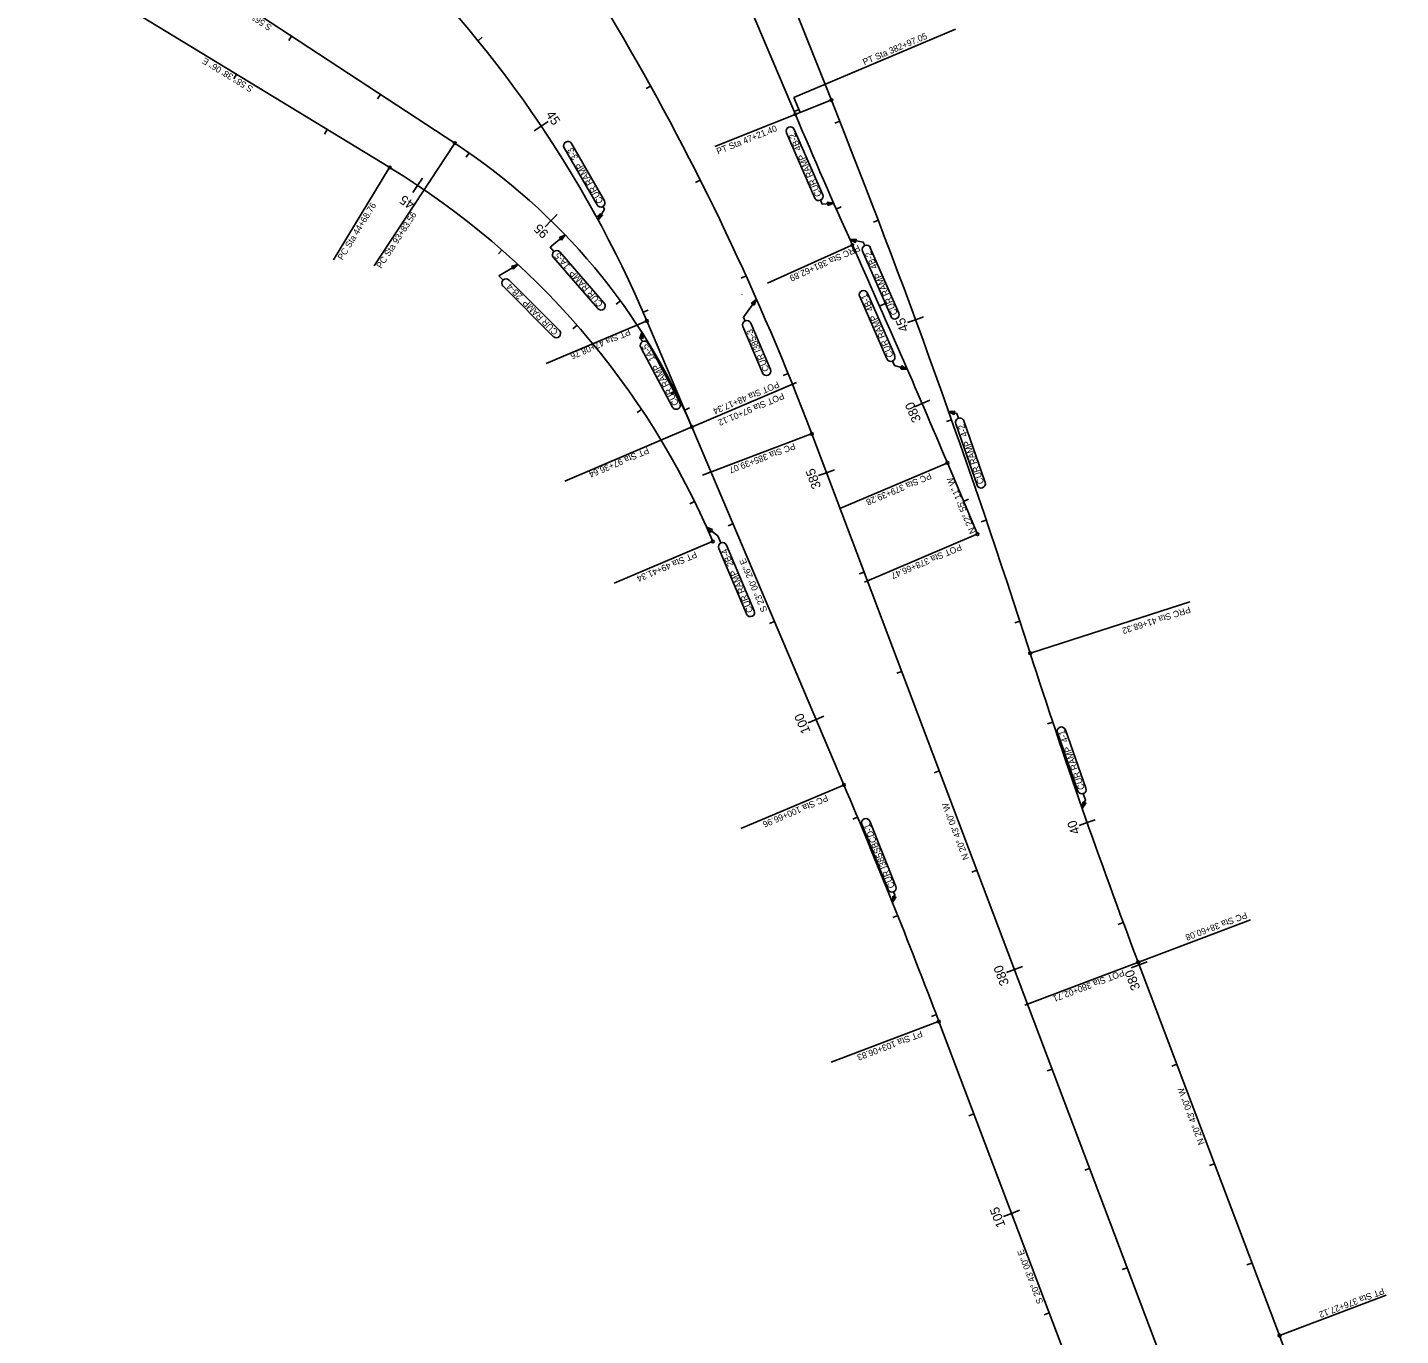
# Model space of a CAD drawing. Extents: x 1603540 to 1622629, y 1083934 to 1103503.
# Drawn here: x 1610826 to 1612118, y 1091966 to 1093197 of the extents above; entities that cross this region are included whole.
import ezdxf

# ---------------------------------------------------------------- set-up
doc = ezdxf.new("R2010")
doc.units = 0
for name, color, linetype in [('RD_EX_BldgChurch', 7, 'Continuous'), ('RD_EX_Fence_ChLk', 7, 'Continuous'), ('RD_EX_H2O', 7, 'Continuous'), ('RD_EX_Misc', 7, 'Continuous'), ('RD_HC_CL', 7, 'Continuous'), ('RD_PG_GR', 7, 'Continuous')]:
    doc.layers.add(name, color=color, linetype=linetype)

msp = doc.modelspace()

# ---------------------------------------------------------------- linework, layer by layer
at = {"layer": 'RD_EX_BldgChurch'}
for p, q in [((1611547.2, 1093131.3), (1611699.4, 1093195.7)), ((1611581.5, 1093128.4), (1611473, 1093085.2)), ((1611547.2, 1093131.3), (1611553.2, 1093117.1)), ((1611227.6, 1093087.2), (1611152.6, 1092972.9)), ((1611166.4, 1093064.3), (1611114.1, 1092978.5)), ((1611601.2, 1092991.9), (1611522.6, 1092956.5)), ((1611498.8, 1092945.8), (1611498.4, 1092945.7)), ((1611407.8, 1092920.6), (1611314.4, 1092880.9)), ((1611452.5, 1092821.6), (1611549.7, 1092862.9)), ((1611452.5, 1092821.6), (1611546.8, 1092861.7)), ((1611450.2, 1092820.7), (1611331.7, 1092770.3)), ((1611562.9, 1092814.3), (1611461.2, 1092775.8)), ((1611690.6, 1092786.9), (1611590.4, 1092744.6)), ((1611718.9, 1092719.9), (1611613.6, 1092675.3)), ((1611469.9, 1092713), (1611378.3, 1092674.1)), ((1611770.7, 1092608.8), (1611919.8, 1092656.6)), ((1611593.2, 1092483.9), (1611497.5, 1092443.3)), ((1611872.3, 1092317.9), (1611976.9, 1092357.5)), ((1611869.9, 1092317), (1611764.4, 1092277.1)), ((1611682.5, 1092261.4), (1611582.4, 1092223.5)), ((1612005.1, 1091966.6), (1612104.5, 1092004.2))]:
    msp.add_line(p, q, dxfattribs=at)
for centre in [(1611582.6, 1093128.9), (1611548.7, 1093115.4), (1611228.3, 1093088.3), (1611167.1, 1093065.3), (1611602.3, 1092992.4), (1611408.9, 1092921.1), (1611451.4, 1092821.2), (1611451.4, 1092821.2), (1611564.1, 1092814.8), (1611691.7, 1092787.4), (1611720.1, 1092720.3), (1611471, 1092713.5), (1611769.5, 1092608.4), (1611594.4, 1092484.4), (1611871.1, 1092317.5), (1611683.7, 1092261.8), (1612004, 1091966.2)]:
    msp.add_circle(centre, 1.25, dxfattribs=at)
at = {"layer": 'RD_EX_H2O'}
for p, q in [((1611074.8, 1093189), (1611072.1, 1093184.8)), ((1611250.2, 1093184.7), (1611254.1, 1093187.9)), ((1611023, 1093153.2), (1611020.4, 1093148.9)), ((1611158.5, 1093134.1), (1611155.7, 1093129.9)), ((1611412.5, 1093142), (1611408.2, 1093139.6)), ((1611547.6, 1093118.1), (1611552.2, 1093120)), ((1611309.7, 1093104.4), (1611316.3, 1093108.8)), ((1611590.5, 1093109), (1611585.9, 1093107.1)), ((1611108.4, 1093101.1), (1611105.7, 1093096.9)), ((1611309.7, 1093104.4), (1611303, 1093099.9)), ((1611241.9, 1093079.1), (1611239.1, 1093075)), ((1611193.4, 1093048.5), (1611197.8, 1093055.2)), ((1611193.4, 1093048.5), (1611189, 1093041.9)), ((1611459.2, 1093053.6), (1611454.8, 1093051.3)), ((1611318.9, 1093015.4), (1611324.5, 1093021.1)), ((1611361.6, 1093018.9), (1611365.9, 1093021.3)), ((1611587.2, 1093026.3), (1611591.8, 1093028.3)), ((1611318.9, 1093015.4), (1611313.3, 1093009.6)), ((1611626.7, 1093015.8), (1611622.1, 1093014)), ((1611272.7, 1092987.7), (1611269.4, 1092984)), ((1611502.4, 1092963.4), (1611497.8, 1092961.3)), ((1611384.2, 1092939.8), (1611380.1, 1092936.8)), ((1611405.5, 1092929.1), (1611410.1, 1092931.1)), ((1611627.9, 1092934.9), (1611632.5, 1092937)), ((1611343.3, 1092917), (1611339.5, 1092913.7)), ((1611661.8, 1092922.1), (1611654.3, 1092919.4)), ((1611661.8, 1092922.1), (1611669.3, 1092924.9)), ((1611541.8, 1092871.5), (1611537.2, 1092869.6)), ((1611436, 1092854.4), (1611431.6, 1092852.2)), ((1611404, 1092837.7), (1611399.9, 1092834.9)), ((1611444.6, 1092837.1), (1611449.2, 1092839.1)), ((1611667.9, 1092843.3), (1611660.6, 1092840.1)), ((1611667.9, 1092843.3), (1611675.3, 1092846.4)), ((1611695.6, 1092828), (1611690.9, 1092826.3)), ((1611577.9, 1092778.2), (1611570.4, 1092775.4)), ((1611577.9, 1092778.2), (1611585.4, 1092781)), ((1611453.9, 1092751), (1611449.4, 1092748.8)), ((1611707, 1092751.2), (1611711.6, 1092753.2)), ((1611728.3, 1092733.5), (1611723.6, 1092731.9)), ((1611490, 1092730.1), (1611485.4, 1092728.2)), ((1611613.3, 1092684.7), (1611608.6, 1092682.9)), ((1611529.1, 1092638.1), (1611524.5, 1092636.1)), ((1611759.8, 1092638.6), (1611755, 1092637)), ((1611648.7, 1092591.1), (1611644, 1092589.4)), ((1611568.2, 1092546), (1611560.8, 1092542.9)), ((1611568.2, 1092546), (1611575.6, 1092549.2)), ((1611790.8, 1092543.5), (1611786, 1092541.9)), ((1611684, 1092497.6), (1611679.4, 1092495.8)), ((1611607.2, 1092454), (1611602.6, 1092452)), ((1611823.1, 1092448.9), (1611815.6, 1092446.2)), ((1611823.1, 1092448.9), (1611830.7, 1092451.6)), ((1611719.4, 1092404.1), (1611714.7, 1092402.3)), ((1611645, 1092361.4), (1611640.4, 1092359.5)), ((1611857.1, 1092354.8), (1611852.4, 1092353.1)), ((1611754.8, 1092310.5), (1611747.3, 1092307.7)), ((1611754.8, 1092310.5), (1611762.3, 1092313.4)), ((1611872.1, 1092314.9), (1611864.6, 1092312.1)), ((1611872.1, 1092314.9), (1611879.6, 1092317.8)), ((1611681.3, 1092268.2), (1611676.6, 1092266.4)), ((1611790.2, 1092217), (1611785.5, 1092215.2)), ((1611907.4, 1092221.4), (1611902.8, 1092219.6)), ((1611716.6, 1092174.7), (1611712, 1092172.9)), ((1611942.8, 1092127.9), (1611938.1, 1092126.1)), ((1611825.5, 1092123.5), (1611820.9, 1092121.7)), ((1611752, 1092081.1), (1611744.5, 1092078.3)), ((1611752, 1092081.1), (1611759.5, 1092084)), ((1611860.9, 1092029.9), (1611856.2, 1092028.2)), ((1611978.2, 1092034.3), (1611973.5, 1092032.6)), ((1611787.4, 1091987.6), (1611782.7, 1091985.8))]:
    msp.add_line(p, q, dxfattribs=at)
at = {"layer": 'RD_HC_CL'}
for p, q in [((1611582.6, 1093128.9), (1611474, 1093401.3)), ((1610826.4, 1093352.1), (1611228.3, 1093088.3)), ((1611548.7, 1093115.4), (1611482.5, 1093272)), ((1610851.4, 1093257.7), (1611167.1, 1093065.3)), ((1611408.9, 1092921.1), (1611451.4, 1092821.2)), ((1611451.4, 1092821.2), (1611594.4, 1092484.4)), ((1612051.1, 1091527.2), (1611564.1, 1092814.8)), ((1611720.1, 1092720.3), (1611691.7, 1092787.4)), ((1612004, 1091966.2), (1611871.1, 1092317.5)), ((1611683.7, 1092261.8), (1611849.6, 1091823.2))]:
    msp.add_line(p, q, dxfattribs=at)
for centre, radius, start, end in [((1609225.7, 1091930.4), 2500, 20.7167, 39.6334), ((1610396.4, 1092491.2), 1100, 23.0073, 46.3737), ((1604151.3, 1090166.4), 8000, 17.77323, 21.73435), ((1617075, 1095452), 6000, 202.91963, 204.20083), ((1610899.1, 1092586.6), 600, 23.0073, 56.724), ((1610771.5, 1092416.4), 760, 23.0073, 58.635), ((1602481.2, 1088893), 10000, 22.91963, 24.20083), ((1617483.2, 1094439.9), 6000, 197.77323, 200.71665), ((1606071.6, 1090139.3), 6000, 20.71665, 23.00726), ((1613874.7, 1092673.7), 2000, 200.7167, 208.5554)]:
    msp.add_arc(centre, radius, start, end, dxfattribs=at)
at = {"layer": 'RD_PG_GR'}
for p, q in [((1611540.3, 1093098.1), (1611567.1, 1093036.6)), ((1611574.4, 1093039.8), (1611547.7, 1093101.3)), ((1611331.2, 1093083.9), (1611362.2, 1093030.1)), ((1611369.1, 1093034.1), (1611338.2, 1093087.9)), ((1611321.2, 1092980.7), (1611362.9, 1092932.6)), ((1611368.9, 1092937.8), (1611327.2, 1092985.9)), ((1611611.9, 1092986.7), (1611638.7, 1092925.2)), ((1611646, 1092928.4), (1611619.2, 1092989.9)), ((1611273.7, 1092953.7), (1611321, 1092906.3)), ((1611326.7, 1092911.9), (1611279.4, 1092959.4)), ((1611609.2, 1092944), (1611634.8, 1092885.3)), ((1611642.1, 1092888.5), (1611616.5, 1092947.2)), ((1611499.4, 1092915.7), (1611517.8, 1092872.1)), ((1611525.2, 1092875.2), (1611506.7, 1092918.8)), ((1611403.3, 1092896.1), (1611433.1, 1092839.9)), ((1611440.2, 1092843.6), (1611410.4, 1092899.9)), ((1611699.7, 1092824.3), (1611719.7, 1092766.4)), ((1611727.2, 1092769), (1611707.2, 1092826.9)), ((1611476.6, 1092706.9), (1611502.7, 1092645.2)), ((1611510, 1092648.3), (1611483.9, 1092710)), ((1611795.2, 1092533.6), (1611814.4, 1092478.6)), ((1611821.9, 1092481.2), (1611802.7, 1092536.2)), ((1611643.3, 1092388.9), (1611618.7, 1092450.3)), ((1611611.3, 1092447.3), (1611635.9, 1092385.9))]:
    msp.add_line(p, q, dxfattribs=at)
for points in [[(1611572.4, 1093034.6), (1611574, 1093030.8), (1611584.8, 1093031.7)], [(1611367.6, 1093028.7), (1611369, 1093026.3), (1611363.2, 1093015.9)], [(1611321.6, 1092986.3), (1611318.1, 1092990.3), (1611332.3, 1093001.9)], [(1611614, 1092991.9), (1611612.6, 1092995.1), (1611600, 1092997.5)], [(1611273.7, 1092959.4), (1611269.8, 1092963.3), (1611287.8, 1092974.1)], [(1611501.5, 1092920.9), (1611499.9, 1092924.6), (1611512.2, 1092941.5)], [(1611405, 1092901.5), (1611403.8, 1092903.6), (1611404.2, 1092910.4)], [(1611640, 1092883.2), (1611641.8, 1092879.1), (1611654, 1092875.6)], [(1611702.1, 1092829.4), (1611700.6, 1092833.9), (1611692.6, 1092835.8)], [(1611478.7, 1092712.2), (1611475.9, 1092718.7), (1611465.1, 1092727)], [(1611819.5, 1092476.1), (1611821.5, 1092470.2), (1611818.4, 1092462.3)], [(1611641.1, 1092383.7), (1611642.3, 1092380.8), (1611640.1, 1092373.6)]]:
    msp.add_lwpolyline(points, dxfattribs=at)
for points in [[(1611579.1, 1093029.7), (1611584.8, 1093031.7), (1611578.9, 1093032.7)], [(1611364.7, 1093021.7), (1611363.2, 1093015.9), (1611367.4, 1093020.2)], [(1611328.8, 1092997), (1611332.3, 1093001.9), (1611326.8, 1092999.4)], [(1611606, 1092997.9), (1611600, 1092997.5), (1611605.4, 1092994.9)], [(1611283.6, 1092969.8), (1611287.8, 1092974.1), (1611282.1, 1092972.4)], [(1611510, 1092935.9), (1611512.2, 1092941.5), (1611507.5, 1092937.7)], [(1611405.4, 1092904.6), (1611404.2, 1092910.4), (1611402.3, 1092904.7)], [(1611648, 1092875.7), (1611654, 1092875.6), (1611648.8, 1092878.7)], [(1611698.6, 1092836), (1611692.6, 1092835.8), (1611697.9, 1092833)], [(1611470.7, 1092724.7), (1611465.1, 1092727), (1611468.8, 1092722.2)], [(1611819.1, 1092468.3), (1611818.4, 1092462.3), (1611822, 1092467.1)], [(1611640.3, 1092379.5), (1611640.1, 1092373.6), (1611643.3, 1092378.7)]]:
    msp.add_lwpolyline(points, close=True, dxfattribs=at)
for centre, start, end in [((1611544, 1093099.7), 23.5602, 203.5602), ((1611334.7, 1093085.9), 29.9145, 209.9145), ((1611365.6, 1093032.1), 209.9145, 29.9145), ((1611570.8, 1093038.2), 203.5602, 23.5602), ((1611615.6, 1092988.3), 23.5602, 203.5602), ((1611324.2, 1092983.3), 40.9145, 220.9145), ((1611276.5, 1092956.6), 44.9145, 224.9145), ((1611612.8, 1092945.6), 23.5602, 203.5602), ((1611365.9, 1092935.2), 220.9145, 40.9145), ((1611642.3, 1092926.8), 203.5602, 23.5602), ((1611503, 1092917.3), 22.9145, 202.9145), ((1611323.9, 1092909.1), 224.9145, 44.9145), ((1611406.8, 1092898), 27.9145, 207.9145), ((1611638.4, 1092886.9), 203.5602, 23.5602), ((1611521.5, 1092873.6), 202.9145, 22.9145), ((1611436.6, 1092841.8), 207.9145, 27.9145), ((1611703.4, 1092825.6), 19.0506, 199.0506), ((1611723.4, 1092767.7), 199.0506, 19.0506), ((1611480.3, 1092708.5), 22.9145, 202.9145), ((1611506.4, 1092646.7), 202.9145, 22.9145), ((1611799, 1092534.9), 19.2449, 199.2449), ((1611818.2, 1092479.9), 199.2449, 19.2449), ((1611615, 1092448.8), 21.862, 201.862), ((1611639.6, 1092387.4), 201.862, 21.862)]:
    msp.add_arc(centre, 4, start, end, dxfattribs=at)

# ---------------------------------------------------------------- texts
at = {"layer": 'RD_EX_BldgChurch'}
for s, rotation, p in [('PT Sta 382+97.05', 22.9196, (1611613.6, 1093161.6)), ('PT Sta 47+21.40', 21.7343, (1611475.9, 1093077.5)), ('PC Sta 44+68.76', 58.635, (1611122.8, 1092977.7)), ('PC Sta 93+83.56', 56.724, (1611159.1, 1092969.8)), ('PRC Sta 381+62.89', 204.2008, (1611607.9, 1092992.7)), ('PT Sta 47+08.76', 203.0073, (1611392, 1092913.8)), ('POT Sta 48+17.34', 203.0073, (1611532, 1092864.4)), ('POT Sta 97+01.12', 203.0073, (1611536.7, 1092853.6)), ('PT Sta 97+36.64', 203.0073, (1611409.5, 1092802.3)), ('PC Sta 385+39.07', 200.7167, (1611547.3, 1092806.3)), ('PC Sta 379+39.28', 202.9196, (1611675.2, 1092778.3)), ('POT Sta 378+66.47', 202.9196, (1611703.6, 1092711.2)), ('PT Sta 49+41.34', 203.0073, (1611454.6, 1092704.3)), ('PRC Sta 41+68.32', 197.7732, (1611919.3, 1092652.4)), ('PC Sta 100+66.96', 203.0073, (1611577.9, 1092475.2)), ('PC Sta 38+60.08', 200.7167, (1611972.3, 1092364.9)), ('POT Sta 380+02.71', 200.7167, (1611856.8, 1092310.7)), ('PT Sta 103+06.83', 200.7167, (1611666.9, 1092253.3)), ('PT Sta 376+27.12', 200.7167, (1612101.3, 1092011.2))]:
    msp.add_text(s, height=6, rotation=rotation, dxfattribs=at).set_placement(p)
at = {"layer": 'RD_EX_Fence_ChLk'}
for s, rotation, p in [('S 56%%d 43\' 26" E', 146.724, (1611056.8, 1093198.7)), ('S 58%%d 38\' 06" E', 148.635, (1611039.2, 1093141)), ('N 22%%d 55\' 11" W', 112.9196, (1611718.6, 1092722.2)), ('S 23%%d 00\' 26" E', 113.0073, (1611522.5, 1092648.5)), ('N 20%%d 43\' 00" W', 110.7167, (1611712.2, 1092415.1)), ('N 20%%d 43\' 00" W', 110.7514, (1611933.8, 1092147)), ('S 20%%d 43\' 00" E', 110.7167, (1611782, 1091997.3))]:
    msp.add_text(s, height=6, rotation=rotation, dxfattribs=at).set_placement(p)
at = {"layer": 'RD_EX_Misc'}
for s, rotation, p in [('45', 303.8811, (1611313.6, 1093115.1)), ('45', 146.2795, (1611191.1, 1093032.7)), ('95', 135.6045, (1611317.2, 1093004)), ('45', 110.1487, (1611655.4, 1092912.6)), ('380', 113.2676, (1611667.2, 1092827.7)), ('385', 110.7167, (1611573.1, 1092764.8)), ('100', 113.0073, (1611563, 1092534.7)), ('40', 109.3806, (1611816.6, 1092439.6)), ('380', 110.7167, (1611749.9, 1092297.3)), ('380', 110.7167, (1611873.3, 1092293)), ('105', 110.7167, (1611746.4, 1092069.8))]:
    msp.add_text(s, height=8.75, rotation=rotation, dxfattribs=at).set_placement(p)
at = {"layer": 'RD_PG_GR'}
for s, rotation, p in [('CUR RAMP_4B-2', 113.5602, (1611573.5, 1093039.4)), ('CUR RAMP_3-3', 119.9145, (1611368.2, 1093033.6)), ('CUR RAMP_1A-5', 130.9145, (1611368.1, 1092937.2)), ('CUR RAMP_4B-2', 113.5602, (1611645.1, 1092928)), ('CUR RAMP_2B-4', 134.9145, (1611326, 1092911.2)), ('CUR RAMP_4B-1', 113.5602, (1611641.2, 1092888.1)), ('CUR I385-3', 112.9145, (1611524.3, 1092874.8)), ('CUR RAMP_1A-5', 117.9145, (1611439.3, 1092843.2)), ('CUR RAMP_4-2', 109.0506, (1611726.3, 1092768.6)), ('CUR RAMP_2B-4', 112.9145, (1611509.1, 1092647.9)), ('CUR RAMP_4-1', 109.2449, (1611821, 1092480.9)), ('CUR I385SBCD-1', 111.862, (1611642.4, 1092388.5))]:
    msp.add_text(s, height=6, rotation=rotation, dxfattribs=at).set_placement(p)

doc.saveas('drawing.dxf')
